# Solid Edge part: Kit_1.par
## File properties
Sűrűség: 0,000 kg/m^3
Pontosság: 0,990
Author: ahadarics
Last saved by: psaghy
Revision: 77
Username: ahadarics
Dokumentum tartalom típus: 0
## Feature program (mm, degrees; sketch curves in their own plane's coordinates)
base feature "unnamed BaseFeature 1"
sketch for "Furat_1" plane through (0, 0, -129.5) normal (0, 0, -1) x-axis (0, 1, 0)
  hole centre (-28.25, 28.25) bore radius 3.3235
hole "Furat_1" nominal diameter 8 finite  VBottomAngle = 118 deg; ThreadDepth = 16 mm
sketch for "unnamed Hole 1" plane through (0, 0, -129.5) normal (0, 0, -1) x-axis (0, 1, 0)
  hole centre (-28.25, -28.25) bore radius 3.3235
hole "unnamed Hole 1" finite
sketch for "unnamed Hole 2" plane through (0, 0, -129.5) normal (0, 0, -1) x-axis (0, 1, 0)
  hole centre (28.25, -28.25) bore radius 3.3235
hole "unnamed Hole 2" finite
sketch for "unnamed Hole 3" plane through (0, 0, -129.5) normal (0, 0, -1) x-axis (0, 1, 0)
  hole centre (28.25, 28.25) bore radius 3.3235
hole "unnamed Hole 3" finite
pattern "unnamed Pattern 1" of "Furat_1", "unnamed Hole 1", "unnamed Hole 2", "unnamed Hole 3"
sketch for "Furat_5" plane through (37.5, -0.0062, -110.7488) normal (1, 0, 0) x-axis (0, 0, -1)
hole "Furat_5" diameter 16.662 finite  ThreadDepth = 17 mm
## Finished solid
Body 1: solid body, 402 faces, 974 edges, 624 vertices, 4 internal voids.
  Faces by surface: cylinder 158, plane 137, cone 35, torus 34, spline 27, sphere 7, swept 4
  Edges by curve: curve on surface 351, line 333, circle 278, spline 12
Bounding box of the edges (mm; curved faces can reach further): 75.001 x 75.000 x 37.500, from (-37.5, -37.5, -133.5) to (37.5009, 37.5, -96).
Cylindrical faces by radius (mm): R0.3049 x1, R0.3063 x2, R0.3073 x1, R0.3094 x1, R0.3138 x1, R0.3275 x1, R0.3358 x1, R0.3579 x2, R0.3595 x2, R0.3746 x2, R0.3825 x2, R0.3862 x2, R0.3932 x1, R0.395 x1, R0.3966 x1, R0.3998 x2, R0.4022 x1, R0.4063 x1, R0.4065 x1, R0.4073 x2, R0.4133 x1, R0.4335 x2, R0.4417 x1, R0.4627 x2, R0.4813 x1, R0.4994 x1, R0.5 x3, R0.5004 x1, R0.5051 x1, R0.507 x1, R0.5233 x1, R0.5325 x1, R0.5327 x1, R0.5437 x2, R0.5682 x1, R0.5785 x2, R0.6044 x1, R0.6048 x2, R0.6079 x1, R0.6085 x1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
Conical faces (half-angle, radius in mm at the cone's reference point): 30 deg R5.1443 x1, 32.8285 deg R32.5 x2, 37.7468 deg R33.5 x3, 45 deg R2.25 x3, 45 deg R2.5 x3, 45 deg R2.75 x1, 45 deg R2.825 x1, 45 deg R4.3 x8, 45 deg R6.35 x8, 45 deg R8.075 x1, 59 deg R3.3235 x4
Toroidal faces (ring radius, tube radius in mm): R0.5015 r0.5005 x1, R1 r0.5 x1, R1.0358 r0.5 x1, R1.6 r0.1 x3, R4.3 r0.3 x4, R4.7 r0.3 x1, R6.45 r0.2 x4, R7.15 r0.5 x4, R10.25 r1 x2, R12 r0.5 x1, R22 r0.5 x1, R23 r0.5 x1, R34 r1 x3, R38.0449 r1 x1, R38.5 r1 x6
Spherical faces by radius (mm): R1 x7
Planar faces by outward normal: +x 23, +y 7, +z 12, -x 4, -y 7, -z 29, oblique 55
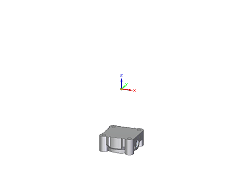
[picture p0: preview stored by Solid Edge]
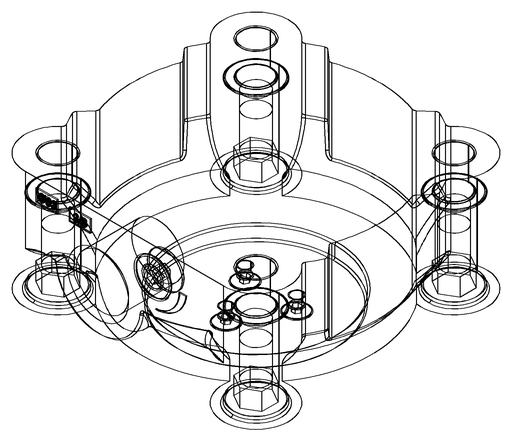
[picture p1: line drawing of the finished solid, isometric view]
